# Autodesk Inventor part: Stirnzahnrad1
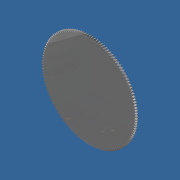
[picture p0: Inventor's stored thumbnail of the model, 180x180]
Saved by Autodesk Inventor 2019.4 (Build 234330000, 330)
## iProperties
Created: 2021-12
Part Number: Stirnzahnrad1
Material: Steel
Document SubType Name: Modeling
Categories: <?xml version="1.0" encoding="UTF-16"?> <MemberInstance><Categories><FamilyTemplate><FamilyTemplateParameter ValueType="xs:double" Id="1" ObjectReferenceKey="da
Mass: 37.7898 g
Surface Area: 70.2712 cm^2
Volume: 4.81399 cm^3
Density: 7.85 g/cm^3
Appearance: Steel
CustomPartVersion: 1
Masse: 0,04 kg
Fläche: 7027,12 mm^2
Volumen: 4813,99 mm^3
Abmasse: 65 mm x 65 mm x 1,5 mm
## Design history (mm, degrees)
sketch "Sketch1"
  geometry: C1 r 32.5 at (0, 0)
  constraints: 1 centre point
  dimensions: "d0" = 65 diameter of C1 (= da_da)
extrude "Extrusion1" new body sketch "Sketch1" distance "d1" = 1.5 (= da_b); taper "d2" = 0 deg
workplane "Work Plane2"
sketch "Sketch2"
  geometry: C1 r 32.5 at (0, 0) reference; C2 r 32 at (0, 0)
  constraints: 1 centre point, 1 coincident
  dimensions: "d3" = 64 diameter of C2 (= da_dw)
feature "Flankendurchmesser" sketch "Sketch2" dims "d4" = 10, "d5" = 0
workplane "Work Plane8"
workplane "Work Plane9"
feature "Stirnzahnrad" dims "da_b" = 1.5, "da_d" = 64, "da_aw" = 35.5, "da_da" = 65, "da_df" = 62.75, "da_dw" = 64, angle "da_beta" = 0 deg, "da_lefttooth" = 0, "da_righttooth" = 0
body "Solid1"
body "Srf1"
other parameters: "d16" = 35.5 (= da_aw), "d17" = 0, "d34" = 0.24544 (computed from da_z), "d39" = 0, "d41" = 0, "d43" = 35.5 (= da_aw), "d46" = 35.5 (= da_aw), "d47" = 0, "d48" = 0
